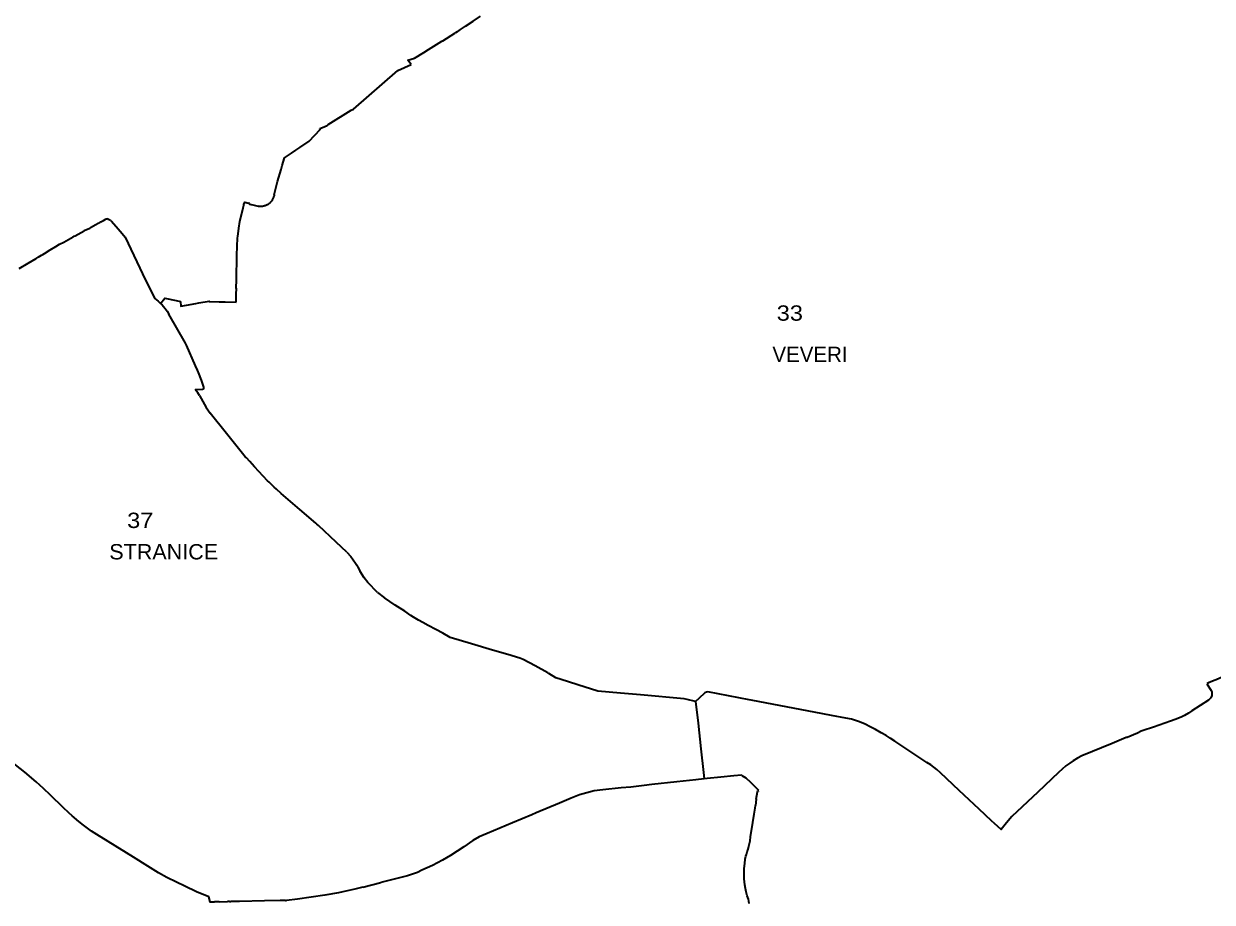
# Model space of a CAD drawing. Extents: x -610940 to -588976, y -1170376 to -1149800.
# Drawn here: x -600249 to -598311, y -1160628 to -1159195 of the extents above; entities that cross this region are included whole.
import ezdxf

# ---------------------------------------------------------------- set-up
doc = ezdxf.new("R2010")
doc.units = 0
doc.header["$LTSCALE"] = 10
doc.layers.add('54', color=7, linetype='Continuous', lineweight=35)
doc.layers.add('55', color=7, linetype='Continuous')
doc.layers.add('56', color=7, linetype='Continuous')

msp = doc.modelspace()

# ---------------------------------------------------------------- linework, layer by layer
at = {"layer": '54'}
for p, q in [((-599542.12, -1159207.85), (-599541.44, -1159207.44)), ((-599766.51, -1159365.89), (-599762.49, -1159364.15)), ((-599762.49, -1159364.15), (-599754.56, -1159360.73)), ((-599881.59, -1159488.1), (-599883.03, -1159487.7)), ((-599881.59, -1159488.1), (-599881.75, -1159488.99)), ((-600132.03, -1159522.66), (-600127.95, -1159520.32)), ((-600123.55, -1159517.81), (-600119.66, -1159515.68)), ((-600119.66, -1159515.68), (-600115.27, -1159513.19)), ((-600115.27, -1159513.19), (-600113.41, -1159513.36)), ((-600111.88, -1159513.73), (-600113.41, -1159513.36)), ((-600111.88, -1159513.73), (-600110.31, -1159514.35)), ((-600110.31, -1159514.35), (-600109.05, -1159515.03)), ((-600107.73, -1159515.98), (-600109.05, -1159515.03)), ((-600107.73, -1159515.98), (-600106.57, -1159517.09)), ((-600150.81, -1159532.39), (-600141.91, -1159528.31)), ((-599900.05, -1159537.72), (-599898.98, -1159528.64)), ((-600242.07, -1159585.3), (-600229.19, -1159577.66)), ((-600218.63, -1159571.29), (-600215.77, -1159569.57)), ((-600256.89, -1159594.38), (-600242.07, -1159585.3)), ((-600000.72, -1159646.63), (-599994, -1159648.08)), ((-599930.68, -1159648.45), (-599924.07, -1159648.56)), ((-599985.71, -1159716.21), (-600012.85, -1159668.55)), ((-599984.11, -1159719.09), (-599985.71, -1159716.21)), ((-599969.31, -1159753.11), (-599984.11, -1159719.09)), ((-599966.24, -1159760.18), (-599969.31, -1159753.11)), ((-599965.22, -1159762.52), (-599966.24, -1159760.18)), ((-599964.72, -1159763.75), (-599965.22, -1159762.52)), ((-599959.66, -1159776.28), (-599964.72, -1159763.75)), ((-599969.81, -1159791.33), (-599958.27, -1159791.2)), ((-599965.81, -1159796.89), (-599969.81, -1159791.33)), ((-599955.75, -1159787.55), (-599959.66, -1159776.28)), ((-599958.27, -1159791.2), (-599957.24, -1159790.94)), ((-599957.24, -1159790.94), (-599956.67, -1159790.75)), ((-599955.7, -1159788.26), (-599955.75, -1159787.55)), ((-599962.94, -1159801.35), (-599965.81, -1159796.89)), ((-599918.8, -1159863.43), (-599945.39, -1159830.39)), ((-599897.08, -1159890.32), (-599918.8, -1159863.43)), ((-599888.35, -1159901.21), (-599897.08, -1159890.32)), ((-599886.42, -1159902.9), (-599888.35, -1159901.21)), ((-599880.94, -1159909.13), (-599886.42, -1159902.9)), ((-599873.22, -1159917.84), (-599880.94, -1159909.13)), ((-599851.83, -1159940.43), (-599873.22, -1159917.84)), ((-599849.35, -1159942.91), (-599851.83, -1159940.43)), ((-599840.96, -1159951.06), (-599849.35, -1159942.91)), ((-599837.47, -1159954.27), (-599840.96, -1159951.06)), ((-599829.62, -1159961.28), (-599837.47, -1159954.27)), ((-599799.04, -1159987.23), (-599829.62, -1159961.28)), ((-599773.09, -1160009.38), (-599799.04, -1159987.23)), ((-599771.3, -1160011), (-599773.09, -1160009.38)), ((-599768.82, -1160013.48), (-599771.3, -1160011)), ((-599739.93, -1160040.41), (-599768.82, -1160013.48)), ((-599722.37, -1160056.97), (-599739.93, -1160040.41)), ((-599722.37, -1160056.97), (-599715.88, -1160064.05)), ((-599715.88, -1160064.05), (-599708.41, -1160074.82)), ((-599704.82, -1160081.15), (-599700.67, -1160088.64)), ((-599694.45, -1160098.7), (-599700.67, -1160088.64)), ((-599688.39, -1160106.63), (-599694.45, -1160098.7)), ((-599672.7, -1160122.83), (-599688.39, -1160106.63)), ((-599672.7, -1160122.83), (-599661.38, -1160131.54)), ((-599643.84, -1160143.22), (-599661.38, -1160131.54)), ((-599627.86, -1160153.38), (-599643.84, -1160143.22)), ((-599618.32, -1160160.08), (-599627.86, -1160153.38)), ((-599614.1, -1160162.79), (-599618.32, -1160160.08)), ((-599606.03, -1160167.81), (-599614.1, -1160162.79)), ((-599598.97, -1160171.85), (-599606.03, -1160167.81)), ((-599589.85, -1160176.79), (-599598.97, -1160171.85)), ((-599577.51, -1160183.27), (-599589.85, -1160176.79)), ((-599566.35, -1160189.17), (-599577.51, -1160183.27)), ((-599554.03, -1160195.93), (-599566.35, -1160189.17)), ((-599519.07, -1160206.35), (-599554.03, -1160195.93)), ((-599484.95, -1160216.58), (-599519.07, -1160206.35)), ((-599460.3, -1160223.91), (-599484.95, -1160216.58)), ((-599440.39, -1160229.89), (-599460.3, -1160223.91)), ((-599435.12, -1160231.76), (-599440.39, -1160229.89)), ((-599415.69, -1160242.15), (-599435.12, -1160231.76)), ((-599394.82, -1160253.98), (-599415.69, -1160242.15)), ((-599393.07, -1160254.98), (-599394.82, -1160253.98)), ((-599381.78, -1160262.07), (-599393.07, -1160254.98)), ((-599362.83, -1160268.07), (-599381.78, -1160262.07)), ((-599344.38, -1160273.94), (-599362.83, -1160268.07)), ((-599325.24, -1160279.92), (-599344.38, -1160273.94)), ((-598317.5, -1160270.19), (-598320.43, -1160271.45)), ((-598320.43, -1160271.45), (-598313.13, -1160282.59)), ((-599313.16, -1160283.56), (-599325.24, -1160279.92)), ((-599276.62, -1160287.06), (-599313.16, -1160283.56)), ((-599244, -1160289.87), (-599276.62, -1160287.06)), ((-599172.74, -1160296.02), (-599244, -1160289.87)), ((-599167.63, -1160297.2), (-599172.74, -1160296.02)), ((-599153.88, -1160300.38), (-599167.63, -1160297.2)), ((-598313.83, -1160294.57), (-598317.48, -1160298.05)), ((-598312.22, -1160290.79), (-598313.83, -1160294.57)), ((-598313.13, -1160282.59), (-598312.26, -1160284.8)), ((-598433.43, -1160351.92), (-598450.26, -1160359.03)), ((-598427.42, -1160348.8), (-598433.43, -1160351.92)), ((-598423.79, -1160348.02), (-598427.42, -1160348.8)), ((-598406.97, -1160342.43), (-598423.79, -1160348.02)), ((-598451.52, -1160359.29), (-598474.49, -1160369.16)), ((-598450.26, -1160359.03), (-598451.52, -1160359.29)), ((-599091.76, -1160421.97), (-599112.94, -1160424.13)), ((-599091.36, -1160421.93), (-599091.76, -1160421.97)), ((-599079.17, -1160420.67), (-599091.36, -1160421.93)), ((-599078.37, -1160421.06), (-599079.17, -1160420.67)), ((-599078.37, -1160421.06), (-599071.9, -1160425.02)), ((-599063.23, -1160433.36), (-599071.9, -1160425.02)), ((-599060.12, -1160436.66), (-599063.23, -1160433.36)), ((-599058.97, -1160437.72), (-599060.12, -1160436.66)), ((-599057.32, -1160439.4), (-599058.97, -1160437.72)), ((-599050.88, -1160445.47), (-599057.32, -1160439.4)), ((-599054.86, -1160459.58), (-599052.99, -1160447.69)), ((-599052.99, -1160447.69), (-599052.28, -1160446.32)), ((-599052.28, -1160446.32), (-599050.88, -1160445.47)), ((-599056.82, -1160474.22), (-599056.24, -1160470.26)), ((-599054.86, -1160459.58), (-599056.24, -1160470.26)), ((-599060.56, -1160498.09), (-599058.4, -1160484.39)), ((-599058.4, -1160484.39), (-599056.82, -1160474.22)), ((-599064.39, -1160521.37), (-599060.56, -1160498.09)), ((-599065.76, -1160531.88), (-599065.03, -1160527.56)), ((-599065.03, -1160527.56), (-599064.39, -1160521.37)), ((-599071.81, -1160552.97), (-599071, -1160549.78)), ((-599071, -1160549.78), (-599069.82, -1160545.72)), ((-599069.82, -1160545.72), (-599068.19, -1160541.14)), ((-599068.19, -1160541.14), (-599066.85, -1160536.55)), ((-599066.85, -1160536.55), (-599065.76, -1160531.88)), ((-599074.59, -1160573.24), (-599074.26, -1160568.78)), ((-599074.26, -1160568.78), (-599073.84, -1160564.92)), ((-599073.84, -1160564.92), (-599072.81, -1160557.79)), ((-599072.81, -1160557.79), (-599071.81, -1160552.97)), ((-599623.72, -1160584.86), (-599664.82, -1160595.15)), ((-599607.27, -1160579.16), (-599623.72, -1160584.86)), ((-599074.83, -1160578.63), (-599074.59, -1160573.24)), ((-599074.8, -1160584.58), (-599074.83, -1160578.63)), ((-599074.5, -1160589.57), (-599074.8, -1160584.58)), ((-599664.82, -1160595.15), (-599666.94, -1160595.69)), ((-599074.1, -1160594.68), (-599074.5, -1160589.57)), ((-599073.41, -1160599.62), (-599074.1, -1160594.68)), ((-599072.45, -1160605.29), (-599073.41, -1160599.62)), ((-599071.32, -1160611.08), (-599072.45, -1160605.29)), ((-599945.69, -1160627.27), (-599938.52, -1160627.22)), ((-599945.32, -1160628.56), (-599945.69, -1160627.27)), ((-599931.02, -1160627.04), (-599917.47, -1160626.86)), ((-599913.75, -1160626.78), (-599917.47, -1160626.86)), ((-599913.75, -1160626.78), (-599911.59, -1160626.72)), ((-599908.66, -1160626.66), (-599911.59, -1160626.72)), ((-599822.46, -1160624.97), (-599821.1, -1160624.93)), ((-599802.91, -1160623.13), (-599821.1, -1160624.93)), ((-599069.9, -1160617.23), (-599071.32, -1160611.08)), ((-599068.84, -1160620.31), (-599069.9, -1160617.23)), ((-599067.59, -1160623.12), (-599068.84, -1160620.31)), ((-599066.9, -1160626.17), (-599067.59, -1160623.12)), ((-599066.41, -1160629.92), (-599066.9, -1160626.17))]:
    msp.add_line(p, q, dxfattribs=at)
for points in [[(-599541.44, -1159207.44), (-599537.14, -1159204.47), (-599529, -1159199.09), (-599516.51, -1159190.7), (-599504.46, -1159182.56)], [(-599617.97, -1159261.21), (-599623.3, -1159254.17), (-599612.04, -1159250.89), (-599597.06, -1159241.64), (-599589.25, -1159236.86), (-599567.5, -1159223.44), (-599566.32, -1159222.73), (-599546.37, -1159210.44), (-599544.69, -1159209.42), (-599542.12, -1159207.85)], [(-599715.33, -1159336.17), (-599711.99, -1159334.2), (-599639.42, -1159271.36), (-599617.97, -1159261.21)], [(-599754.56, -1159360.73), (-599752.96, -1159359.16), (-599715.33, -1159336.17)], [(-599828.08, -1159426.23), (-599824.53, -1159413.91), (-599824.16, -1159413.66), (-599813.07, -1159406.19), (-599805.85, -1159401.31), (-599799.07, -1159396.81), (-599784.15, -1159386.4), (-599765.93, -1159367.38), (-599766.51, -1159365.89)], [(-599841.07, -1159474.24), (-599835.57, -1159452.5), (-599829.98, -1159432.89), (-599829.3, -1159430.46), (-599828.08, -1159426.23)], [(-599841.07, -1159474.24), (-599841.39, -1159475.35), (-599841.72, -1159476.47), (-599842.06, -1159477.39), (-599842.45, -1159478.3), (-599842.8, -1159479.16), (-599843.16, -1159480.01), (-599843.64, -1159480.99), (-599844.16, -1159481.95), (-599844.65, -1159482.8), (-599845.16, -1159483.64), (-599845.72, -1159484.46), (-599846.32, -1159485.26), (-599846.96, -1159486.04), (-599847.64, -1159486.79), (-599848.36, -1159487.54), (-599849.13, -1159488.24), (-599850.01, -1159488.94), (-599850.93, -1159489.57), (-599851.8, -1159490.11), (-599852.7, -1159490.6), (-599853.7, -1159491.09), (-599854.73, -1159491.53), (-599855.73, -1159491.88), (-599856.74, -1159492.18), (-599857.76, -1159492.43), (-599858.79, -1159492.64), (-599859.91, -1159492.84), (-599861.03, -1159492.99), (-599862.13, -1159493.07), (-599863.23, -1159493.09), (-599864.31, -1159493.06), (-599865.38, -1159492.99), (-599866.41, -1159492.88), (-599867.45, -1159492.77)], [(-599898.98, -1159528.64), (-599896.95, -1159517.75), (-599891.81, -1159495.14), (-599890.64, -1159491.15), (-599890.34, -1159490.06), (-599889.18, -1159485.99), (-599883.03, -1159487.7)], [(-599881.75, -1159488.99), (-599880.7, -1159489.34), (-599880.18, -1159489.48), (-599878.62, -1159489.88), (-599875.99, -1159490.51), (-599867.45, -1159492.77)], [(-600141.91, -1159528.31), (-600140.53, -1159527.55), (-600132.03, -1159522.66)], [(-600127.95, -1159520.32), (-600125.48, -1159518.94), (-600123.55, -1159517.81)], [(-600106.57, -1159517.09), (-600095.29, -1159529.63), (-600088.94, -1159537.03), (-600084.15, -1159543.08), (-600050.91, -1159613.18)], [(-600197.09, -1159558.28), (-600190.96, -1159554.59), (-600184.16, -1159551.14), (-600169.13, -1159542.61)], [(-600169.13, -1159542.61), (-600167.2, -1159541.52), (-600165.81, -1159540.77), (-600151.14, -1159532.65), (-600150.81, -1159532.39)], [(-599903.15, -1159648.95), (-599902.96, -1159635.7), (-599902.92, -1159633.87), (-599902.82, -1159629.07), (-599902.79, -1159627.12), (-599902.94, -1159625.5), (-599902.48, -1159613.19), (-599902.39, -1159599.78), (-599902.07, -1159585.71), (-599901.83, -1159573), (-599901.32, -1159557.77), (-599901.04, -1159544.8), (-599900.46, -1159541.21), (-599900.05, -1159537.72)], [(-600215.77, -1159569.57), (-600206.32, -1159563.86), (-600197.09, -1159558.28)], [(-600229.19, -1159577.66), (-600225.93, -1159575.71), (-600220.47, -1159572.42), (-600218.63, -1159571.29)], [(-600050.91, -1159613.18), (-600035.85, -1159643.34), (-600030.3, -1159647.69), (-600026.35, -1159651.08)], [(-600026.35, -1159651.08), (-600019.33, -1159642.61), (-600000.72, -1159646.63)], [(-600026.35, -1159651.08), (-600023.79, -1159653.65), (-600021.39, -1159656.2), (-600018.7, -1159659.49), (-600015.71, -1159663.78), (-600012.85, -1159668.55)], [(-599994, -1159648.08), (-599993.37, -1159655.71), (-599983.92, -1159653.96), (-599969.05, -1159651.28), (-599964.06, -1159650.4), (-599947.14, -1159647.36), (-599947.25, -1159648.16), (-599930.68, -1159648.45)], [(-599924.07, -1159648.56), (-599921.27, -1159648.58), (-599903.15, -1159648.95)], [(-599956.67, -1159790.75), (-599956.01, -1159789.78), (-599955.88, -1159789.43)], [(-599955.88, -1159789.43), (-599955.79, -1159788.9), (-599955.7, -1159788.26)], [(-599962.94, -1159801.35), (-599952.01, -1159820.99), (-599945.39, -1159830.39)], [(-599708.41, -1160074.82), (-599706.43, -1160078.31), (-599704.82, -1160081.15)], [(-598293.88, -1160260.06), (-598305, -1160264.91), (-598308.36, -1160266.26), (-598317.5, -1160270.19)], [(-598765.48, -1160407.51), (-598770.25, -1160404.04), (-598776.55, -1160399.86), (-598829.24, -1160365.22), (-598836.44, -1160360.44), (-598843.32, -1160356.11), (-598851.08, -1160351.44), (-598860.25, -1160346.15), (-598869.09, -1160341.64), (-598877.54, -1160337.46), (-598886.6, -1160333.66), (-598894.76, -1160330.86), (-598899.75, -1160329.46), (-598909.05, -1160327.51), (-598932.03, -1160323.23), (-598946.56, -1160320.49), (-599063.2, -1160298.52), (-599066.55, -1160297.71), (-599133.94, -1160284.67), (-599136.24, -1160285.08), (-599138.57, -1160286.34), (-599148.84, -1160295.76), (-599153.88, -1160300.38)], [(-598317.48, -1160298.05), (-598344.4, -1160315.82), (-598350.1, -1160319.46), (-598356.68, -1160323.38), (-598362.24, -1160325.91), (-598371.87, -1160329.72), (-598379.46, -1160332.58), (-598406.97, -1160342.43)], [(-598312.26, -1160284.8), (-598311.88, -1160286.02), (-598311.78, -1160287.28), (-598311.92, -1160288.37), (-598312.09, -1160289.47), (-598312.22, -1160290.79)], [(-600116.15, -1160526.25), (-600126.1, -1160520.21), (-600138.76, -1160511.76), (-600151.84, -1160502.25), (-600159.7, -1160496.34), (-600170.75, -1160487.14), (-600176.1, -1160482.15), (-600185.22, -1160473.25), (-600206.08, -1160453.49), (-600217.54, -1160442.6), (-600229.41, -1160431.52), (-600247.87, -1160415.66), (-600285.71, -1160385.84), (-600332.06, -1160350.1), (-600397.56, -1160299.41)], [(-599153.88, -1160300.38), (-599149.95, -1160335.87), (-599145.33, -1160377.55), (-599141.03, -1160416.32), (-599139.87, -1160426.79)], [(-598474.49, -1160369.16), (-598523.84, -1160389.32), (-598531.03, -1160392.79), (-598537.99, -1160397.06)], [(-598549.93, -1160405.55), (-598561.91, -1160416.43), (-598595.57, -1160448.26), (-598638.03, -1160488.17), (-598646.72, -1160498.28), (-598655.63, -1160509.4), (-598666.66, -1160499.39), (-598671.38, -1160494.98), (-598691.28, -1160476.37), (-598723.92, -1160445.79), (-598754.57, -1160416.66), (-598760.6, -1160411.42), (-598765.48, -1160407.51)], [(-598537.99, -1160397.06), (-598543.79, -1160400.92), (-598549.93, -1160405.55)], [(-599139.87, -1160426.79), (-599153.77, -1160428.34), (-599184.58, -1160431.74), (-599225.06, -1160435.99), (-599237.9, -1160437.33), (-599259.7, -1160439.99), (-599275.15, -1160441.26), (-599305.2, -1160444.51), (-599319.52, -1160446.37), (-599343.08, -1160452.78), (-599356.96, -1160458.21), (-599375.87, -1160466.1), (-599413.91, -1160482.08), (-599421.02, -1160485.08), (-599452.35, -1160498.24), (-599493.84, -1160515.68)], [(-599112.94, -1160424.13), (-599134.9, -1160426.3), (-599139.87, -1160426.79)], [(-599945.69, -1160627.27), (-599947.92, -1160619.35), (-599967.59, -1160610.68), (-599986.75, -1160601.72), (-600000.45, -1160595.4), (-600016.14, -1160587.57), (-600029.82, -1160579.77), (-600047.03, -1160569.17), (-600070.48, -1160554.56), (-600111.58, -1160529.03), (-600116.15, -1160526.25)], [(-599493.84, -1160515.68), (-599506.89, -1160521.3), (-599517.25, -1160527.26), (-599531.66, -1160537.34), (-599553.8, -1160551.63), (-599566.82, -1160559.52), (-599582.76, -1160567.83), (-599600.11, -1160575.69), (-599607.27, -1160579.16)], [(-599696.66, -1160603.22), (-599709.6, -1160606.57), (-599729.12, -1160611.21), (-599736.02, -1160612.63), (-599758.31, -1160616.61), (-599802.91, -1160623.13)], [(-599696.66, -1160603.22), (-599682.06, -1160599.55), (-599666.94, -1160595.69)], [(-599931.02, -1160627.04), (-599938.13, -1160627.17), (-599938.52, -1160627.22)], [(-599822.46, -1160624.97), (-599824.85, -1160625.23), (-599827.9, -1160625.24), (-599831.3, -1160625.3), (-599856.9, -1160625.7), (-599897.68, -1160626.45), (-599908.66, -1160626.66)]]:
    msp.add_lwpolyline(points, dxfattribs=at)

# ---------------------------------------------------------------- texts
at = {"layer": '55'}
msp.add_text('VEVERI ', height=25, dxfattribs=at).set_placement((-599028.64, -1159746.75))
at = {"layer": '55', "width": 1.05}
msp.add_text('STRANICE ', height=25, dxfattribs=at).set_placement((-600110.02, -1160068.73))
at = {"layer": '56', "width": 1.15}
for s, p in [('33 ', (-599021.56, -1159679.35)), ('37 ', (-600080.92, -1160017.49))]:
    msp.add_text(s, height=25, dxfattribs=at).set_placement(p)

doc.saveas('drawing.dxf')
